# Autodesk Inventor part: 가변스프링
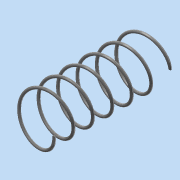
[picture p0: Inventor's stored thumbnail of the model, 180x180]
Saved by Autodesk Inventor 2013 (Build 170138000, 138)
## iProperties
Created: 2016-11
Part Number: 가변스프링
Material: 강철, 탄소
Document SubType Name: Modeling
Designer: Administrator
Mass: -0.0756758 g
Surface Area: 38.0291 cm^2
Volume: -0.00961573 cm^3
Density: 7.87 g/cm^3
Author: Administrator
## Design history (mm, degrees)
sketch "스케치1"
  geometry: L1 (0, 0)-(16, 0); L2 (16, 0)-(16, 84.368); L3 (16, 84.368)-(0, 84.368); L4 (0, 84.368)-(0, 0); C1 r 1 at (16, 0)
  constraints: 8 end point, 2 parallel, 1 centre point, 1 coincident, 1 horizontal, 1 perpendicular
  dimensions: "d0" = 32 diameter of L2 L4; "d2" = 84.36759 distance between parallel lines of L1 L3 (derived); "d3" = 2 diameter of C1
feature "코일1" sketch "스케치1" pitch "d4" = 10; turns "d6" = 6; dims "d5" = 84.36759 (= d2), "d7" = 0, angle "d8" = 90 deg, angle "d9" = 90 deg, "d10" = 0, "d11" = 0
feature "분할1"
node "작업 평면1"
feature "분할2"
node "솔리드1"
other parameters: "d12" = 90 deg
